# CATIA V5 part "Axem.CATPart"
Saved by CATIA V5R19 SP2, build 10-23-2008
Part number: Axem
Bounding box of the stored display mesh (mm): x 0 to 150, y -5 to 5, z -4.99 to 4.99
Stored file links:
  C:\Users\Vianney\Documents\Garantie\Cours\2A\IAO\IAO-proj-Catia\Axem.CATPart
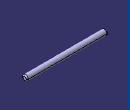
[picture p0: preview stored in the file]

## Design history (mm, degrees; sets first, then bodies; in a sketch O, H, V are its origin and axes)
Parameters
  Dmc = 10 mm
Body1 (main body)
  Sketch1 on yz-plane, origin (0, 0, 0), H (0, 1, 0), V (0, 0, 1)
    circle A1 centre (0, 0) radius 5
    radius A1 = 5 {= Dmc /2}
  Pad1: profile Sketch1, direction (1, 0, 0), length 150
  Fillet1: radius 2, on edge [face of Pad1 from Sketch1.A1 | end face of Pad1]; edge [start face of Pad1 | face of Pad1 from Sketch1.A1]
